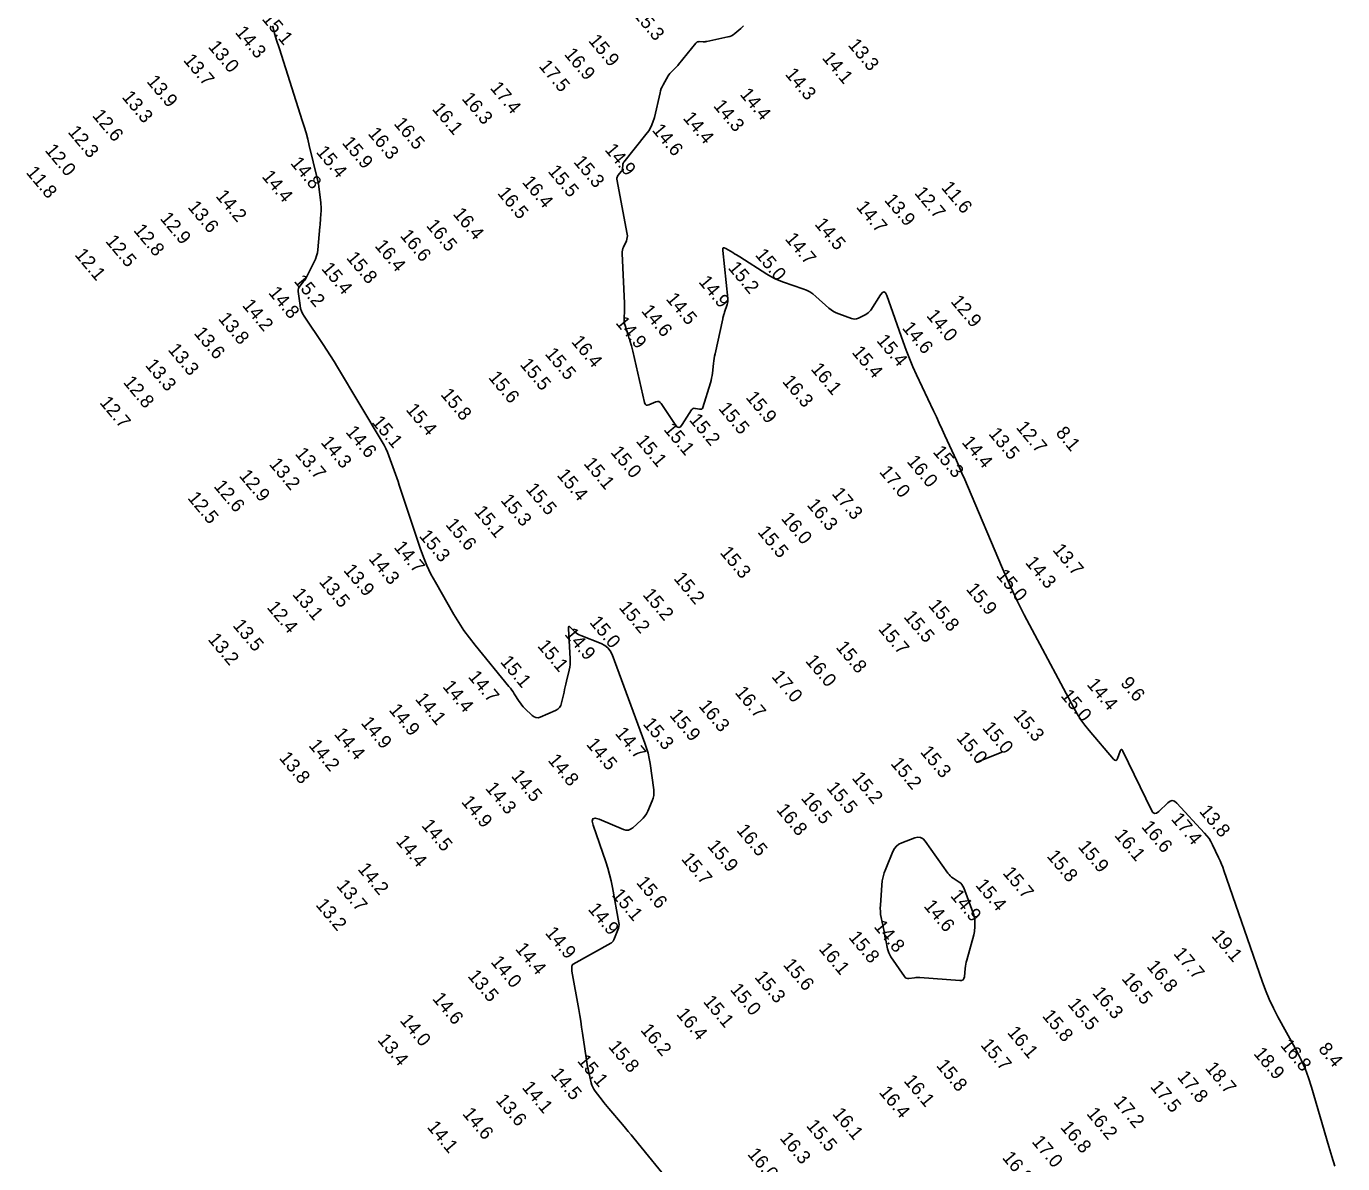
# Model space of a CAD drawing. Extents: x 988130 to 1132882, y 654656 to 841453.
# Drawn here: x 1109709.3 to 1110197.5, y 680751.5 to 681173.2 of the extents above; entities that cross this region are included whole.
import ezdxf

# ---------------------------------------------------------------- set-up
doc = ezdxf.new("R2010")
doc.units = 0
doc.layers.add('V-TOPO-MAJR', color=7, linetype='Continuous')
doc.layers.add('V-TOPO-SOUN', color=7, linetype='Continuous')

msp = doc.modelspace()

# ---------------------------------------------------------------- linework, layer by layer
at = {"layer": 'V-TOPO-MAJR'}
for points in [[(1109949.29, 680742.91), (1109934.63, 680760.91), (1109933.59, 680762.17), (1109932.55, 680763.43), (1109931.51, 680764.68), (1109930.46, 680765.93), (1109925.41, 680771.88), (1109924.77, 680772.65), (1109924.14, 680773.42), (1109923.52, 680774.19), (1109922.91, 680774.98), (1109920.32, 680778.33), (1109919.83, 680779.04), (1109919.43, 680779.79), (1109919.1, 680780.57), (1109918.85, 680781.4), (1109918.03, 680784.78), (1109917.83, 680785.62), (1109917.65, 680786.47), (1109917.5, 680787.33), (1109917.36, 680788.18), (1109915.61, 680799.8), (1109915.27, 680802.03), (1109914.92, 680804.25), (1109914.55, 680806.46), (1109914.17, 680808.68), (1109911.68, 680822.81), (1109911.64, 680823.05), (1109911.62, 680823.29), (1109911.61, 680823.52), (1109911.62, 680823.76), (1109911.68, 680824.72), (1109911.72, 680824.95), (1109911.81, 680825.14), (1109911.95, 680825.3), (1109912.13, 680825.43), (1109926.15, 680833.22), (1109926.26, 680833.29), (1109926.37, 680833.37), (1109926.47, 680833.46), (1109926.56, 680833.56), (1109926.9, 680833.99), (1109926.99, 680834.1), (1109927.06, 680834.21), (1109927.13, 680834.33), (1109927.18, 680834.45), (1109928.75, 680838.12), (1109928.98, 680838.77), (1109929.1, 680839.44), (1109929.13, 680840.12), (1109929.05, 680840.82), (1109926.69, 680853.88), (1109926.21, 680856.28), (1109925.63, 680858.65), (1109924.97, 680861), (1109924.21, 680863.33), (1109919.49, 680876.97), (1109919.16, 680878.49), (1109919.43, 680879.37), (1109920.32, 680879.59), (1109921.83, 680879.16), (1109930.75, 680875.42), (1109931.7, 680875.15), (1109932.59, 680875.16), (1109933.44, 680875.45), (1109934.25, 680876.01), (1109937.37, 680878.81), (1109938.1, 680879.54), (1109938.74, 680880.34), (1109939.3, 680881.21), (1109939.76, 680882.14), (1109941.45, 680886.05), (1109941.8, 680887.03), (1109942.01, 680888.04), (1109942.07, 680889.06), (1109942, 680890.1), (1109940.65, 680899.79), (1109940.32, 680901.74), (1109939.89, 680903.66), (1109939.36, 680905.56), (1109938.72, 680907.43), (1109926.55, 680940.24), (1109925.89, 680941.59), (1109925, 680942.72), (1109923.89, 680943.63), (1109922.55, 680944.31), (1109914.95, 680947.26), (1109914.39, 680947.51), (1109913.87, 680947.82), (1109913.38, 680948.17), (1109912.92, 680948.57), (1109911.16, 680950.3), (1109910.78, 680950.6), (1109910.51, 680950.64), (1109910.37, 680950.41), (1109910.35, 680949.93), (1109911.04, 680938.7), (1109911.07, 680937.64), (1109911.01, 680936.59), (1109910.88, 680935.55), (1109910.67, 680934.51), (1109909.65, 680930.32), (1109909.41, 680929.32), (1109909.17, 680928.32), (1109908.95, 680927.31), (1109908.73, 680926.31), (1109907.86, 680922.29), (1109907.55, 680921.35), (1109907.06, 680920.57), (1109906.39, 680919.95), (1109905.54, 680919.47), (1109899.92, 680917.07), (1109899.1, 680916.84), (1109898.33, 680916.85), (1109897.61, 680917.12), (1109896.93, 680917.63), (1109894.23, 680920.29), (1109893.64, 680920.89), (1109893.1, 680921.52), (1109892.59, 680922.19), (1109892.11, 680922.88), (1109890.29, 680925.71), (1109889.82, 680926.41), (1109889.34, 680927.1), (1109888.83, 680927.77), (1109888.31, 680928.43), (1109875.76, 680943.7), (1109873.62, 680946.42), (1109871.6, 680949.21), (1109869.7, 680952.09), (1109867.92, 680955.05), (1109861.03, 680967.06), (1109859.39, 680970.1), (1109857.9, 680973.21), (1109856.58, 680976.39), (1109855.41, 680979.64), (1109847.65, 681003.06), (1109847.19, 681004.43), (1109846.72, 681005.8), (1109846.24, 681007.16), (1109845.74, 681008.52), (1109843.75, 681013.96), (1109843.22, 681015.3), (1109842.63, 681016.62), (1109841.98, 681017.9), (1109841.27, 681019.16), (1109824.79, 681046.78), (1109823.5, 681048.9), (1109822.18, 681051.01), (1109820.83, 681053.1), (1109819.46, 681055.17), (1109812.31, 681065.77), (1109811.77, 681066.67), (1109811.35, 681067.62), (1109811.04, 681068.62), (1109810.85, 681069.65), (1109810.18, 681074.91), (1109810.17, 681075.44), (1109810.26, 681075.94), (1109810.45, 681076.41), (1109810.75, 681076.85), (1109812.17, 681078.55), (1109812.51, 681078.98), (1109812.82, 681079.43), (1109813.11, 681079.89), (1109813.37, 681080.38), (1109816.11, 681085.83), (1109816.6, 681086.92), (1109816.98, 681088.04), (1109817.25, 681089.19), (1109817.42, 681090.37), (1109818.23, 681098.9), (1109818.3, 681099.64), (1109818.35, 681100.39), (1109818.41, 681101.14), (1109818.45, 681101.9), (1109818.61, 681104.9), (1109818.63, 681105.65), (1109818.62, 681106.4), (1109818.58, 681107.15), (1109818.51, 681107.9), (1109817.96, 681112.71), (1109817.82, 681113.76), (1109817.65, 681114.8), (1109817.45, 681115.84), (1109817.22, 681116.87), (1109814.28, 681128.98), (1109813.69, 681131.33), (1109813.06, 681133.68), (1109812.38, 681136.01), (1109811.66, 681138.33), (1109803.19, 681164.88), (1109802.96, 681165.59), (1109802.74, 681166.3), (1109802.51, 681167), (1109802.29, 681167.71), (1109801.4, 681170.54), (1109801.19, 681171.25), (1109801, 681171.97), (1109800.83, 681172.69), (1109800.68, 681173.42)], [(1109975.29, 681173.44), (1109974.85, 681172.89), (1109974.32, 681172.39), (1109972.07, 681170.5), (1109971.48, 681170.07), (1109970.86, 681169.72), (1109970.2, 681169.44), (1109969.5, 681169.25), (1109961.74, 681167.59), (1109961.38, 681167.53), (1109961.02, 681167.48), (1109960.66, 681167.46), (1109960.29, 681167.46), (1109958.83, 681167.52), (1109958.48, 681167.49), (1109958.16, 681167.4), (1109957.88, 681167.22), (1109957.63, 681166.97), (1109951.24, 681159.07), (1109950.93, 681158.7), (1109950.61, 681158.35), (1109950.28, 681158), (1109949.94, 681157.67), (1109948.55, 681156.35), (1109948.22, 681156.01), (1109947.92, 681155.65), (1109947.64, 681155.27), (1109947.39, 681154.86), (1109945.5, 681151.52), (1109945.13, 681150.81), (1109944.82, 681150.09), (1109944.56, 681149.34), (1109944.35, 681148.57), (1109942.23, 681139.44), (1109941.72, 681137.71), (1109941.03, 681136.06), (1109940.16, 681134.51), (1109939.1, 681133.04), (1109930.89, 681122.87), (1109930.73, 681122.64), (1109930.61, 681122.4), (1109930.53, 681122.14), (1109930.49, 681121.86), (1109930.4, 681120.3), (1109930.39, 681120.23), (1109930.38, 681120.15), (1109930.36, 681120.08), (1109930.34, 681120.01), (1109930.25, 681119.72), (1109930.22, 681119.65), (1109930.19, 681119.58), (1109930.15, 681119.52), (1109930.1, 681119.46), (1109928.73, 681117.84), (1109928.52, 681117.54), (1109928.39, 681117.22), (1109928.35, 681116.88), (1109928.38, 681116.52), (1109932.16, 681096.09), (1109932.23, 681095.48), (1109932.2, 681094.87), (1109932.08, 681094.27), (1109931.87, 681093.69), (1109930.82, 681091.37), (1109930.6, 681090.79), (1109930.44, 681090.19), (1109930.36, 681089.57), (1109930.36, 681088.95), (1109931.18, 681070.54), (1109931.2, 681069.84), (1109931.2, 681069.15), (1109931.19, 681068.46), (1109931.17, 681067.76), (1109931.02, 681064.98), (1109931.02, 681064.29), (1109931.08, 681063.61), (1109931.2, 681062.94), (1109931.38, 681062.27), (1109932.52, 681058.69), (1109932.67, 681058.2), (1109932.83, 681057.71), (1109932.98, 681057.21), (1109933.13, 681056.72), (1109933.74, 681054.75), (1109933.89, 681054.25), (1109934.03, 681053.76), (1109934.15, 681053.26), (1109934.27, 681052.76), (1109938.61, 681033.66), (1109938.82, 681033.1), (1109939.16, 681032.78), (1109939.62, 681032.69), (1109940.2, 681032.84), (1109942.76, 681033.92), (1109943.37, 681034.08), (1109943.92, 681034.03), (1109944.4, 681033.77), (1109944.81, 681033.29), (1109949.95, 681025.5), (1109950.62, 681024.74), (1109951.28, 681024.49), (1109951.94, 681024.75), (1109952.59, 681025.52), (1109956.02, 681030.95), (1109956.28, 681031.26), (1109956.59, 681031.47), (1109956.95, 681031.56), (1109957.36, 681031.53), (1109959.09, 681031.2), (1109959.48, 681031.19), (1109959.8, 681031.29), (1109960.05, 681031.53), (1109960.21, 681031.88), (1109963.01, 681041.01), (1109963.26, 681041.89), (1109963.47, 681042.78), (1109963.63, 681043.67), (1109963.76, 681044.58), (1109964.18, 681048.2), (1109964.29, 681049.11), (1109964.43, 681050.01), (1109964.59, 681050.91), (1109964.77, 681051.81), (1109967.57, 681064.7), (1109967.62, 681064.91), (1109967.67, 681065.12), (1109967.72, 681065.33), (1109967.78, 681065.53), (1109968.01, 681066.36), (1109968.07, 681066.56), (1109968.13, 681066.77), (1109968.19, 681066.97), (1109968.26, 681067.18), (1109969.19, 681070.05), (1109969.34, 681070.6), (1109969.43, 681071.16), (1109969.46, 681071.72), (1109969.43, 681072.29), (1109967.59, 681090.12), (1109967.61, 681090.73), (1109967.8, 681091.06), (1109968.18, 681091.09), (1109968.74, 681090.85), (1109971.34, 681089.28), (1109971.99, 681088.88), (1109972.64, 681088.48), (1109973.28, 681088.08), (1109973.92, 681087.68), (1109983.97, 681081.28), (1109985.45, 681080.4), (1109986.98, 681079.61), (1109988.55, 681078.91), (1109990.17, 681078.31), (1109997.3, 681075.91), (1109998.62, 681075.39), (1109999.88, 681074.74), (1110001.06, 681073.97), (1110002.16, 681073.07), (1110007, 681068.74), (1110007.82, 681068.07), (1110008.69, 681067.49), (1110009.62, 681066.99), (1110010.6, 681066.58), (1110015.29, 681064.88), (1110015.95, 681064.71), (1110016.6, 681064.67), (1110017.25, 681064.77), (1110017.89, 681065), (1110020.43, 681066.21), (1110021.03, 681066.54), (1110021.57, 681066.95), (1110022.05, 681067.43), (1110022.46, 681067.99), (1110026.12, 681073.64), (1110026.82, 681074.48), (1110027.45, 681074.71), (1110028, 681074.34), (1110028.48, 681073.36), (1110034.47, 681056.2), (1110035.6, 681053.09), (1110036.8, 681050.03), (1110038.09, 681046.99), (1110039.46, 681043.98), (1110045.73, 681030.66), (1110046.81, 681028.35), (1110047.89, 681026.05), (1110048.95, 681023.74), (1110050.01, 681021.43), (1110054.24, 681012.18), (1110055.29, 681009.86), (1110056.32, 681007.54), (1110057.34, 681005.21), (1110058.34, 681002.87), (1110071.38, 680972.15), (1110073.92, 680966.36), (1110076.58, 680960.63), (1110079.37, 680954.97), (1110082.29, 680949.37), (1110097.78, 680920.45), (1110099.05, 680918.23), (1110100.43, 680916.09), (1110101.92, 680914.03), (1110103.52, 680912.05), (1110112.57, 680901.45), (1110113, 680901.06), (1110113.38, 680900.97), (1110113.7, 680901.19), (1110113.97, 680901.7), (1110114.93, 680904.37), (1110115.17, 680904.87), (1110115.44, 680905.05), (1110115.72, 680904.9), (1110116.02, 680904.43), (1110126.59, 680882.5), (1110127.14, 680881.68), (1110127.78, 680881.32), (1110128.49, 680881.44), (1110129.29, 680882.02), (1110132.66, 680885.29), (1110133.5, 680885.9), (1110134.32, 680886.08), (1110135.14, 680885.85), (1110135.94, 680885.2), (1110146.3, 680874.05), (1110147.16, 680873.06), (1110147.93, 680872.01), (1110148.62, 680870.91), (1110149.22, 680869.74), (1110151.48, 680864.99), (1110152.03, 680863.79), (1110152.54, 680862.58), (1110153.02, 680861.36), (1110153.47, 680860.12), (1110167.64, 680819.19), (1110168.9, 680815.78), (1110170.3, 680812.45), (1110171.83, 680809.17), (1110173.51, 680805.95), (1110180.48, 680793.21), (1110182.13, 680789.99), (1110183.6, 680786.69), (1110184.89, 680783.31), (1110186, 680779.86), (1110192.41, 680757.85), (1110193.5, 680754.18), (1110194.63, 680750.52)], [(1110061.53, 680900.23), (1110071.14, 680903.99)]]:
    msp.add_lwpolyline(points, dxfattribs=at)
msp.add_lwpolyline([(1110056.31, 680854.95), (1110056.68, 680854.41), (1110056.96, 680853.8), (1110060.7, 680843.72), (1110060.89, 680843.13), (1110061.02, 680842.53), (1110061.09, 680841.91), (1110061.11, 680841.29), (1110061.06, 680838.79), (1110061.02, 680838.16), (1110060.95, 680837.55), (1110060.84, 680836.94), (1110060.69, 680836.33), (1110058.07, 680826.95), (1110057.88, 680826.2), (1110057.72, 680825.44), (1110057.59, 680824.67), (1110057.5, 680823.89), (1110057.21, 680820.78), (1110057.04, 680820.11), (1110056.71, 680819.64), (1110056.19, 680819.39), (1110055.5, 680819.34), (1110040.75, 680820.49), (1110040.23, 680820.52), (1110039.7, 680820.52), (1110039.18, 680820.49), (1110038.66, 680820.43), (1110036.58, 680820.15), (1110036.09, 680820.15), (1110035.65, 680820.27), (1110035.27, 680820.51), (1110034.95, 680820.88), (1110029.95, 680828.18), (1110029.53, 680828.87), (1110029.18, 680829.59), (1110028.91, 680830.34), (1110028.71, 680831.13), (1110028.06, 680834.32), (1110027.89, 680835.12), (1110027.73, 680835.92), (1110027.57, 680836.72), (1110027.41, 680837.52), (1110026.35, 680842.73), (1110026.16, 680843.87), (1110026.05, 680845.02), (1110026.02, 680846.16), (1110026.06, 680847.32), (1110026.6, 680854.72), (1110026.78, 680856.28), (1110027.08, 680857.82), (1110027.5, 680859.33), (1110028.04, 680860.81), (1110030.67, 680867.24), (1110031.24, 680868.33), (1110031.99, 680869.23), (1110032.92, 680869.96), (1110034.03, 680870.49), (1110038.82, 680872.27), (1110039.96, 680872.53), (1110040.99, 680872.42), (1110041.9, 680871.93), (1110042.69, 680871.08), (1110051.1, 680859.22), (1110051.52, 680858.68), (1110051.98, 680858.19), (1110052.49, 680857.74), (1110053.04, 680857.34), (1110055.33, 680855.84), (1110055.86, 680855.43)], close=True, dxfattribs=at)

# ---------------------------------------------------------------- texts
at = {"layer": 'V-TOPO-SOUN'}
for s, p in [('15.3 ', (1109934.24, 681177.41)), ('15.1 ', (1109796.48, 681175.86)), ('14.3 ', (1109786.53, 681170.87)), ('15.9 ', (1109917.55, 681167.8)), ('13.3 ', (1110013.81, 681166.19)), ('13.0 ', (1109776.51, 681165.52)), ('16.9 ', (1109908.57, 681162.75)), ('14.1 ', (1110004.21, 681161.39)), ('13.7 ', (1109767.33, 681160.54)), ('17.5 ', (1109899.18, 681158.34)), ('13.9 ', (1109753.72, 681152.67)), ('14.3 ', (1109990.5, 681155.34)), ('13.3 ', (1109744.55, 681146.88)), ('17.4 ', (1109881.09, 681150.25)), ('14.4 ', (1109973.73, 681147.87)), ('16.1 ', (1109859.57, 681142.47)), ('16.3 ', (1109870.57, 681146.3)), ('14.3 ', (1109963.9, 681143.6)), ('12.6 ', (1109733.58, 681140)), ('16.5 ', (1109845.39, 681137.01)), ('14.4 ', (1109952.6, 681139.08)), ('12.3 ', (1109724.48, 681133.94)), ('16.3 ', (1109835.76, 681133.34)), ('14.6 ', (1109941.17, 681134.61)), ('12.0 ', (1109715.99, 681127.14)), ('15.9 ', (1109826.17, 681129.9)), ('14.9 ', (1109923.64, 681127.32)), ('14.8 ', (1109807.04, 681122.37)), ('15.4 ', (1109816.56, 681126.51)), ('15.3 ', (1109912.03, 681122.85)), ('11.8 ', (1109709, 681118.91)), ('14.4 ', (1109796.44, 681117.41)), ('15.5 ', (1109902.52, 681119.36)), ('16.4 ', (1109892.98, 681115.32)), ('11.6 ', (1110048.39, 681113.31)), ('14.2 ', (1109779.32, 681110.16)), ('16.5 ', (1109883.81, 681111.24)), ('13.9 ', (1110027.3, 681108.63)), ('12.7 ', (1110038.45, 681111.3)), ('13.6 ', (1109768.94, 681106.08)), ('16.4 ', (1109867.3, 681103.52)), ('14.7 ', (1110016.86, 681106.09)), ('12.9 ', (1109758.66, 681101.87)), ('16.5 ', (1109857.39, 681099.22)), ('14.5 ', (1110001.45, 681099.73)), ('12.5 ', (1109738.46, 681093.43)), ('12.8 ', (1109748.84, 681097.47)), ('16.6 ', (1109847.72, 681095.45)), ('14.7 ', (1109990.47, 681094.27)), ('12.1 ', (1109727.03, 681088.43)), ('16.4 ', (1109838.31, 681091.69)), ('15.0 ', (1109979.39, 681088.36)), ('15.4 ', (1109818.53, 681083.26)), ('15.8 ', (1109827.77, 681087.24)), ('15.2 ', (1109969.32, 681083.55)), ('15.2 ', (1109808.35, 681078.64)), ('14.9 ', (1109958.41, 681078.35)), ('14.8 ', (1109798.88, 681074.31)), ('14.2 ', (1109789.18, 681069.63)), ('14.5 ', (1109946.32, 681072.01)), ('12.9 ', (1110051.89, 681071.07)), ('13.8 ', (1109780.26, 681064.7)), ('14.6 ', (1109937.16, 681067.56)), ('14.0 ', (1110042.91, 681065.81)), ('13.6 ', (1109771.27, 681059.3)), ('14.9 ', (1109927.64, 681063.17)), ('14.6 ', (1110033.89, 681061.24)), ('16.4 ', (1109911.22, 681056.16)), ('15.4 ', (1110024.4, 681056.56)), ('13.3 ', (1109761.62, 681053.2)), ('15.5 ', (1109901.46, 681051.62)), ('15.4 ', (1110015.25, 681052.23)), ('13.3 ', (1109753.2, 681047.43)), ('15.5 ', (1109892.16, 681047.69)), ('16.1 ', (1110000.04, 681046.01)), ('12.8 ', (1109745.02, 681041.12)), ('15.6 ', (1109880.45, 681042.92)), ('16.3 ', (1109989.45, 681041.41)), ('15.8 ', (1109862.76, 681036.55)), ('15.9 ', (1109975.91, 681035.47)), ('12.7 ', (1109736.28, 681033.59)), ('15.4 ', (1109849.86, 681030.95)), ('15.5 ', (1109965.78, 681031.39)), ('15.1 ', (1109837.19, 681026.35)), ('15.2 ', (1109954.91, 681027.17)), ('14.6 ', (1109827.51, 681022.68)), ('15.1 ', (1109945.45, 681023.62)), ('13.5 ', (1110065.95, 681022.01)), ('12.7 ', (1110076.14, 681024.37)), ('8.1', (1110090.86, 681022.31)), ('14.3 ', (1109818.27, 681018.83)), ('15.0 ', (1109925.76, 681015.19)), ('15.1 ', (1109935.19, 681019.32)), ('15.3 ', (1110045.28, 681015.31)), ('14.4 ', (1110056, 681018.86)), ('13.2 ', (1109799.14, 681010.73)), ('13.7 ', (1109808.74, 681014.61)), ('15.1 ', (1109915.8, 681010.95)), ('16.0 ', (1110035.63, 681011.74)), ('12.9 ', (1109787.99, 681006.42)), ('15.4 ', (1109905.87, 681006.7)), ('17.0 ', (1110025.42, 681007.9)), ('12.6 ', (1109778.61, 681002.54)), ('15.5 ', (1109894.31, 681001.46)), ('12.5 ', (1109768.89, 680998.22)), ('15.3 ', (1109885, 680997.33)), ('16.3 ', (1109998.57, 680995.64)), ('17.3 ', (1110007.81, 680999.79)), ('15.1 ', (1109875.19, 680993.08)), ('16.0 ', (1109988.99, 680990.62)), ('15.6 ', (1109864.56, 680988.35)), ('15.5 ', (1109980.28, 680985.58)), ('15.3 ', (1109854.78, 680984.08)), ('14.7 ', (1109845.39, 680979.93)), ('15.3 ', (1109966.33, 680977.95)), ('13.7 ', (1110089.7, 680978.93)), ('13.9 ', (1109826.72, 680971.37)), ('14.3 ', (1109836.02, 680975.69)), ('14.3 ', (1110079.55, 680974.24)), ('13.5 ', (1109817.63, 680967.16)), ('15.2 ', (1109949.16, 680968.38)), ('15.0 ', (1110068.82, 680969.45)), ('13.1 ', (1109807.78, 680962.47)), ('15.2 ', (1109937.67, 680962.35)), ('15.9 ', (1110057.62, 680964.39)), ('12.4 ', (1109798.31, 680957.63)), ('15.2 ', (1109928.85, 680957.6)), ('15.8 ', (1110043.6, 680958.32)), ('15.0 ', (1109917.96, 680952.11)), ('15.5 ', (1110034.45, 680954.15)), ('13.5 ', (1109785.66, 680950.92)), ('14.9 ', (1109908.7, 680947.69)), ('15.7 ', (1110025.01, 680949.66)), ('13.2 ', (1109776.44, 680945.78)), ('15.1 ', (1109898.64, 680943.34)), ('15.8 ', (1110009.32, 680942.83)), ('15.1 ', (1109884.85, 680937.46)), ('16.0 ', (1109998.03, 680937.75)), ('14.7 ', (1109872.95, 680931.9)), ('17.0 ', (1109985.47, 680931.98)), ('14.4 ', (1109863.46, 680928.25)), ('14.4 ', (1110102.38, 680929.04)), ('9.6', (1110114.84, 680929.52)), ('14.1 ', (1109853.31, 680923.63)), ('16.7 ', (1109971.89, 680926.07)), ('15.0 ', (1110092.7, 680924.88)), ('14.9 ', (1109843.56, 680919.59)), ('15.9 ', (1109947.64, 680917.61)), ('16.3 ', (1109958.43, 680921.06)), ('15.3 ', (1110075.11, 680917.51)), ('14.9 ', (1109833.15, 680914.8)), ('15.3 ', (1109937.77, 680914.41)), ('15.0 ', (1110063.64, 680912.93)), ('14.4 ', (1109823.23, 680910.65)), ('14.7 ', (1109927.43, 680910.9)), ('15.0 ', (1110054.03, 680909.17)), ('14.2 ', (1109813.79, 680906.44)), ('14.5 ', (1109916.76, 680906.86)), ('15.3 ', (1110040.61, 680904.01)), ('13.8 ', (1109802.85, 680901.79)), ('14.8 ', (1109902.51, 680900.96)), ('15.2 ', (1110029.63, 680899.71)), ('14.5 ', (1109888.9, 680895.13)), ('15.2 ', (1110015.26, 680894.37)), ('14.3 ', (1109879.34, 680890.55)), ('15.5 ', (1110005.85, 680890.66)), ('14.9 ', (1109870.42, 680885.53)), ('16.5 ', (1109996.38, 680886.88)), ('16.8 ', (1109987.25, 680882.56)), ('17.4 ', (1110133.63, 680879.17)), ('13.8 ', (1110144.08, 680882.01)), ('14.5 ', (1109855.65, 680876.77)), ('16.5 ', (1109972.48, 680874.96)), ('16.6 ', (1110122.64, 680876.26)), ('14.4 ', (1109846.18, 680870.9)), ('15.9 ', (1109961.63, 680869.14)), ('15.9 ', (1110099.09, 680868.91)), ('16.1 ', (1110112.61, 680873.13)), ('15.7 ', (1109951.96, 680864.36)), ('15.8 ', (1110087.56, 680865.39)), ('14.2 ', (1109831.99, 680860.6)), ('15.7 ', (1110071.19, 680859.14)), ('13.7 ', (1109824.09, 680854.4)), ('15.6 ', (1109935.3, 680855.58)), ('15.4 ', (1110061.1, 680854.63)), ('15.1 ', (1109926.22, 680850.98)), ('14.9 ', (1110051.77, 680850.7)), ('13.2 ', (1109816.4, 680847.35)), ('14.9 ', (1109917.39, 680845.74)), ('14.6 ', (1110041.89, 680846.89)), ('14.8 ', (1110023.41, 680839.26)), ('14.9 ', (1109901.49, 680836.91)), ('15.8 ', (1110014.02, 680835.29)), ('19.1 ', (1110148.62, 680835.8)), ('14.4 ', (1109890.41, 680831.01)), ('16.1 ', (1110002.97, 680831)), ('14.0 ', (1109881.32, 680826.16)), ('15.6 ', (1109989.77, 680825.1)), ('16.8 ', (1110124.6, 680824.49)), ('17.7 ', (1110134.53, 680829.24)), ('13.5 ', (1109872.77, 680820.94)), ('15.3 ', (1109979.16, 680820.53)), ('16.5 ', (1110115.29, 680819.98)), ('15.0 ', (1109970.09, 680815.91)), ('14.6 ', (1109859.68, 680812.55)), ('15.1 ', (1109960.1, 680811.46)), ('15.5 ', (1110095.27, 680810.45)), ('16.3 ', (1110104.43, 680814.64)), ('16.4 ', (1109950.19, 680806.77)), ('15.8 ', (1110085.84, 680806.15)), ('14.0 ', (1109847.62, 680804.45)), ('16.2 ', (1109936.87, 680800.9)), ('16.1 ', (1110072.87, 680800.01)), ('13.4 ', (1109839.32, 680797.2)), ('15.7 ', (1110062.98, 680795.39)), ('16.8 ', (1110174.17, 680795.21)), ('15.8 ', (1109924.91, 680794.74)), ('18.9 ', (1110164.22, 680792.19)), ('8.4', (1110188.24, 680793.87)), ('15.1 ', (1109913.4, 680789.47)), ('15.8 ', (1110046.57, 680787.73)), ('18.7 ', (1110146.3, 680786.77)), ('14.5 ', (1109903.58, 680784.55)), ('16.1 ', (1110034.5, 680782.05)), ('17.8 ', (1110135.89, 680783.51)), ('14.1 ', (1109892.89, 680779.62)), ('16.4 ', (1110025.31, 680777.83)), ('17.5 ', (1110125.9, 680779.91)), ('13.6 ', (1109883.19, 680774.86)), ('17.2 ', (1110112.28, 680774.23)), ('14.6 ', (1109870.84, 680769.87)), ('16.1 ', (1110008.03, 680769.82)), ('16.2 ', (1110102.28, 680769.91)), ('14.1 ', (1109857.73, 680764.92)), ('15.5 ', (1109998.33, 680765.43)), ('16.8 ', (1110092.58, 680764.84)), ('16.3 ', (1109988.52, 680760.82)), ('17.0 ', (1110082, 680759.5)), ('16.0 ', (1109976.53, 680754.88)), ('16.8 ', (1110071, 680753.59))]:
    msp.add_text(s, height=5, rotation=310, dxfattribs=at).set_placement(p)

doc.saveas('drawing.dxf')
